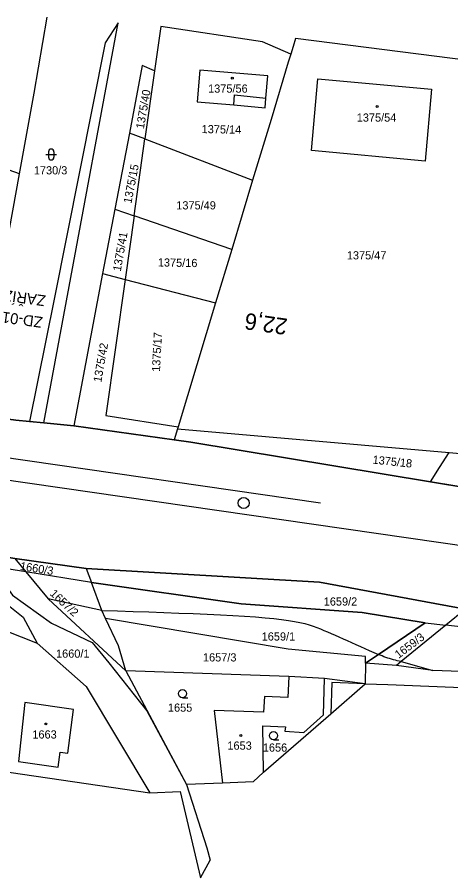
# Model space of a CAD drawing. Extents: x -757895 to -757311, y -1060303 to -1059942.
# Drawn here: x -757525.7 to -757446.3, y -1060221.2 to -1060063.5 of the extents above; entities that cross this region are included whole.
import ezdxf

# ---------------------------------------------------------------- set-up
doc = ezdxf.new("R2010")
doc.units = 0
for name, color, linetype in [('_hektaky', 7, 'Continuous'), ('_SO 102 hektometry', 7, 'Continuous'), ('Dočasné zábory - čísla', 7, 'Continuous'), ('Pozemky SŽDC', 7, 'Continuous'), ('Vrstva 1', 7, 'Continuous'), ('Vrstva 53', 7, 'Continuous'), ('Vrstva 55', 7, 'Continuous'), ('Vrstva 56', 7, 'Continuous'), ('Vrstva 57', 7, 'Continuous'), ('Vrstva 58', 7, 'Continuous'), ('Vrstva 59', 7, 'Continuous')]:
    doc.layers.add(name, color=color, linetype=linetype)

msp = doc.modelspace()

# ---------------------------------------------------------------- linework, layer by layer
at = {"layer": '_SO 102 hektometry'}
msp.add_circle((-757484.25, -1060152.51), 1, dxfattribs=at)
at = {"layer": 'Pozemky SŽDC'}
for points in [[(-757419.22, -1060153.71), (-757450.04, -1060148.6), (-757493.93, -1060141.33), (-757496.99, -1060140.91), (-757515.4, -1060138.37), (-757520.85, -1060137.84), (-757523.49, -1060137.59), (-757525.99, -1060137.35), (-757528.28, -1060137.03), (-757533.01, -1060136.32), (-757534.03, -1060136.19), (-757535.86, -1060133.35), (-757568.62, -1060130.44), (-757606.63, -1060125.23), (-757624.32, -1060124.22), (-757624.54, -1060126.42), (-757639.93, -1060124.17), (-757687.19, -1060114.38)], [(-757686.64, -1060138.39), (-757635.44, -1060145.86), (-757634.26, -1060145.96), (-757632.1, -1060146.3), (-757543.88, -1060160.4), (-757542.9, -1060160.49), (-757535.01, -1060161.18), (-757533.6, -1060161.43), (-757526.21, -1060162.71), (-757513.1, -1060164.5), (-757470.38, -1060167.04), (-757443.58, -1060171.99)]]:
    msp.add_lwpolyline(points, dxfattribs=at)
at = {"layer": 'Vrstva 1'}
for p, q in [((-757429.32, -1060162.53), (-757720.62, -1060120.47)), ((-757576.18, -1060137.2), (-757470.2, -1060152.45))]:
    msp.add_line(p, q, dxfattribs=at)
at = {"layer": 'Vrstva 53'}
for points in [[(-757687.19, -1060114.38), (-757639.93, -1060124.17), (-757624.54, -1060126.42), (-757624.32, -1060124.22), (-757612.89, -1060124.84), (-757606.63, -1060125.23), (-757568.62, -1060130.44), (-757535.86, -1060133.35), (-757534.03, -1060136.19), (-757533.01, -1060136.32), (-757528.28, -1060137.03), (-757525.99, -1060137.35), (-757523.49, -1060137.59), (-757520.85, -1060137.84), (-757515.4, -1060138.37), (-757496.99, -1060140.91), (-757493.93, -1060141.33), (-757450.04, -1060148.6), (-757417.66, -1060153.97), (-757412.43, -1060151.61), (-757391.89, -1060154.81), (-757390.25, -1060143), (-757387.56, -1060158.16)], [(-757328.56, -1060183.46), (-757338.29, -1060184.85), (-757361.91, -1060181.63), (-757443.58, -1060171.99), (-757470.38, -1060167.04), (-757513.1, -1060164.5), (-757526.21, -1060162.71), (-757533.6, -1060161.43), (-757535.01, -1060161.18), (-757542.9, -1060160.49), (-757543.88, -1060160.4), (-757632.1, -1060146.3), (-757634.26, -1060145.96), (-757635.44, -1060145.86), (-757686.64, -1060138.39), (-757693.18, -1060137.43), (-757732.62, -1060131.67), (-757793.56, -1060122.78), (-757866, -1060118.97)], [(-757509.58, -1060173.65), (-757510.26, -1060172.2), (-757512.14, -1060167.1), (-757484.68, -1060170.98), (-757462.52, -1060172.6), (-757450.99, -1060174.46), (-757459.56, -1060180.26), (-757461.95, -1060181.88), (-757461.94, -1060180.64), (-757476.1, -1060179.3), (-757509.58, -1060173.65)]]:
    msp.add_lwpolyline(points, dxfattribs=at)
at = {"layer": 'Vrstva 55'}
for p, q in [((-757522.65, -1060077.4), (-757520.23, -1060063.47)), ((-757499.45, -1060065.15), (-757500.59, -1060073.29)), ((-757480.83, -1060068), (-757499.45, -1060065.15)), ((-757475.63, -1060070.26), (-757480.83, -1060068)), ((-757474.75, -1060067.35), (-757475.21, -1060068.86)), ((-757425.51, -1060073.71), (-757474.75, -1060067.35)), ((-757475.21, -1060068.86), (-757475.63, -1060070.26)), ((-757525.35, -1060092.2), (-757579.91, -1060072.75)), ((-757502.84, -1060072.35), (-757505.19, -1060084.71)), ((-757500.59, -1060073.29), (-757502.84, -1060072.35)), ((-757500.59, -1060073.29), (-757502.35, -1060085.79)), ((-757525.35, -1060092.2), (-757522.65, -1060077.4)), ((-757505.19, -1060084.71), (-757507.85, -1060098.68)), ((-757502.35, -1060085.79), (-757505.19, -1060084.71)), ((-757504.33, -1060099.89), (-757502.35, -1060085.79)), ((-757502.35, -1060085.79), (-757482.61, -1060093.33)), ((-757527.8, -1060105.72), (-757525.35, -1060092.2)), ((-757482.61, -1060093.33), (-757486.45, -1060106.04)), ((-757507.85, -1060098.68), (-757510.09, -1060110.45)), ((-757507.85, -1060098.68), (-757504.33, -1060099.89)), ((-757504.33, -1060099.89), (-757505.97, -1060111.52)), ((-757486.45, -1060106.04), (-757504.33, -1060099.89)), ((-757486.45, -1060106.04), (-757489.4, -1060115.81)), ((-757510.09, -1060110.45), (-757515.4, -1060138.37)), ((-757510.09, -1060110.45), (-757505.97, -1060111.52)), ((-757505.97, -1060111.52), (-757489.4, -1060115.81)), ((-757489.4, -1060115.81), (-757496.27, -1060138.53)), ((-757515.4, -1060138.37), (-757496.99, -1060140.91)), ((-757496.4, -1060138.94), (-757496.99, -1060140.91)), ((-757496.27, -1060138.53), (-757496.4, -1060138.94)), ((-757496.4, -1060138.94), (-757446.57, -1060143.26)), ((-757450.04, -1060148.6), (-757417.66, -1060153.97)), ((-757526.21, -1060162.71), (-757513.1, -1060164.5)), ((-757513.1, -1060164.5), (-757512.14, -1060167.1)), ((-757443.58, -1060171.99), (-757447.18, -1060174.91)), ((-757507.2, -1060178.7), (-757509.58, -1060173.65)), ((-757450.99, -1060174.46), (-757447.18, -1060174.91)), ((-757505.82, -1060183.25), (-757507.2, -1060178.7)), ((-757461.95, -1060181.88), (-757461.97, -1060185.63)), ((-757456.27, -1060182.28), (-757461.95, -1060181.88)), ((-757475.98, -1060184.31), (-757505.82, -1060183.25)), ((-757505.82, -1060183.25), (-757494.7, -1060204.13)), ((-757449.6, -1060183.18), (-757456.27, -1060182.28)), ((-757469.46, -1060184.66), (-757475.98, -1060184.31)), ((-757461.97, -1060185.63), (-757469.46, -1060184.66)), ((-757468.3, -1060191.14), (-757461.97, -1060185.63)), ((-757461.97, -1060185.63), (-757457.81, -1060185.8)), ((-757457.81, -1060185.8), (-757442.84, -1060186.4)), ((-757480.62, -1060201.84), (-757468.3, -1060191.14)), ((-757553.73, -1060197.99), (-757501.45, -1060205.62)), ((-757482.5, -1060203.63), (-757480.62, -1060201.84)), ((-757488.16, -1060203.86), (-757494.7, -1060204.13)), ((-757482.5, -1060203.63), (-757488.16, -1060203.86)), ((-757492.15, -1060221.2), (-757490.36, -1060217.94))]:
    msp.add_line(p, q, dxfattribs=at)
for points in [[(-757475.63, -1060070.26), (-757476.07, -1060071.71), (-757479.24, -1060082.21), (-757482.61, -1060093.33)], [(-757486.06, -1060079.54), (-757480.34, -1060080.05), (-757480.18, -1060078.28), (-757479.84, -1060074.24), (-757492.3, -1060073.2), (-757492.76, -1060078.99), (-757486.06, -1060079.54)], [(-757470.67, -1060074.74), (-757449.81, -1060076.66), (-757451.01, -1060089.85), (-757471.85, -1060087.93), (-757470.67, -1060074.74)], [(-757446.57, -1060143.26), (-757435.09, -1060144.26), (-757425.51, -1060073.71)], [(-757505.97, -1060111.52), (-757509.48, -1060136.47), (-757496.27, -1060138.53)], [(-757515.4, -1060138.37), (-757518.94, -1060138.03), (-757520.85, -1060137.84), (-757523.49, -1060137.59), (-757525.99, -1060137.35)], [(-757496.99, -1060140.91), (-757493.93, -1060141.33), (-757450.04, -1060148.6)], [(-757450.04, -1060148.6), (-757448.35, -1060146), (-757446.57, -1060143.26)], [(-757535.4, -1060164.4), (-757534.05, -1060166.5), (-757527.72, -1060171), (-757524.67, -1060173.45), (-757522.06, -1060178.2)], [(-757530.47, -1060164.08), (-757526.6, -1060169.42), (-757519.47, -1060174.52), (-757512.04, -1060178.07), (-757508.94, -1060181.82), (-757502, -1060190.6), (-757494.7, -1060204.13)], [(-757512.14, -1060167.1), (-757524.18, -1060165.15), (-757527.62, -1060164.59), (-757530.47, -1060164.08)], [(-757513.1, -1060164.5), (-757470.38, -1060167.04), (-757443.58, -1060171.99)], [(-757450.99, -1060174.46), (-757462.52, -1060172.6), (-757484.68, -1060170.98), (-757512.14, -1060167.1)], [(-757509.58, -1060173.65), (-757510.26, -1060172.2), (-757512.14, -1060167.1)], [(-757541.4, -1060170.7), (-757539.76, -1060171.25), (-757522.06, -1060178.2)], [(-757461.95, -1060181.88), (-757461.94, -1060180.64), (-757476.1, -1060179.3), (-757509.58, -1060173.65)], [(-757461.95, -1060181.88), (-757459.56, -1060180.26), (-757450.99, -1060174.46)], [(-757447.18, -1060174.91), (-757455.39, -1060181.56), (-757456.27, -1060182.28)], [(-757373.86, -1060183.46), (-757405.36, -1060179.78), (-757434.52, -1060176.38), (-757447.18, -1060174.91)], [(-757522.06, -1060178.2), (-757513.1, -1060186.11), (-757501.45, -1060205.62)], [(-757373.35, -1060185.99), (-757375.27, -1060185.92), (-757449.6, -1060183.18)], [(-757475.98, -1060184.31), (-757476.19, -1060188.18), (-757480.46, -1060187.96), (-757480.61, -1060190.87), (-757489.65, -1060190.56), (-757488.16, -1060203.86)], [(-757480.62, -1060201.84), (-757480.75, -1060193.37), (-757476.57, -1060193.52), (-757476.69, -1060194.3), (-757473.22, -1060194.56), (-757469.64, -1060191.34), (-757469.46, -1060184.66)], [(-757525.5, -1060199.9), (-757518.26, -1060200.9), (-757517.87, -1060198.2), (-757516.44, -1060198.33), (-757515.46, -1060190.37), (-757524.35, -1060189.08), (-757525.5, -1060199.9)], [(-757494.7, -1060204.13), (-757490.98, -1060215.68), (-757490.36, -1060217.94)], [(-757501.45, -1060205.62), (-757495.89, -1060205.36), (-757492.15, -1060221.2)]]:
    msp.add_lwpolyline(points, dxfattribs=at)
at = {"layer": 'Vrstva 56'}
for p, q in [((-757516.7, -1060115.45), (-757507.27, -1060064.51)), ((-757507.27, -1060064.51), (-757509.6, -1060068.17)), ((-757509.6, -1060068.17), (-757518.99, -1060115.13)), ((-757486.06, -1060079.54), (-757485.91, -1060077.7)), ((-757485.91, -1060077.7), (-757480.18, -1060078.28)), ((-757518.99, -1060115.13), (-757523.49, -1060137.59)), ((-757520.85, -1060137.84), (-757516.7, -1060115.45)), ((-757526.21, -1060162.71), (-757524.18, -1060165.15)), ((-757524.18, -1060165.15), (-757520.05, -1060170.1)), ((-757520.05, -1060170.1), (-757505.82, -1060183.25)), ((-757510.26, -1060172.2), (-757520.05, -1060170.1)), ((-757455.39, -1060181.56), (-757449.6, -1060183.18)), ((-757468.07, -1060185.38), (-757468.3, -1060191.14)), ((-757461.97, -1060185.63), (-757468.07, -1060185.38))]:
    msp.add_line(p, q, dxfattribs=at)
for points in [[(-757510.26, -1060172.2), (-757507.38, -1060172.29), (-757504.48, -1060172.38), (-757501.65, -1060172.48), (-757498.87, -1060172.57), (-757496.13, -1060172.67), (-757493.5, -1060172.78), (-757490.97, -1060172.88), (-757488.52, -1060173), (-757486.24, -1060173.12), (-757484.11, -1060173.25), (-757482.11, -1060173.39), (-757480.33, -1060173.53), (-757478.74, -1060173.69), (-757477.31, -1060173.85), (-757476.06, -1060174.03), (-757474.95, -1060174.21), (-757473.95, -1060174.41), (-757473.07, -1060174.62), (-757472.28, -1060174.84), (-757471.54, -1060175.07), (-757470.86, -1060175.32), (-757470.2, -1060175.57), (-757469.55, -1060175.85), (-757468.9, -1060176.13), (-757468.22, -1060176.43), (-757467.51, -1060176.74), (-757466.79, -1060177.06), (-757466.04, -1060177.39), (-757465.27, -1060177.73), (-757464.48, -1060178.07), (-757463.69, -1060178.43), (-757462.87, -1060178.79), (-757462.05, -1060179.15), (-757461.23, -1060179.52), (-757460.39, -1060179.89), (-757459.56, -1060180.26)], [(-757455.39, -1060181.56), (-757455.75, -1060181.49), (-757456.1, -1060181.41), (-757456.46, -1060181.33), (-757456.81, -1060181.23), (-757457.16, -1060181.14), (-757457.51, -1060181.03), (-757457.86, -1060180.92), (-757458.2, -1060180.8), (-757458.55, -1060180.68), (-757458.89, -1060180.54), (-757459.22, -1060180.41), (-757459.56, -1060180.26)]]:
    msp.add_lwpolyline(points, dxfattribs=at)
at = {"layer": 'Vrstva 58'}
for p, q in [((-757520.52, -1060088.64), (-757518.52, -1060088.64)), ((-757520.02, -1060088.14), (-757520.02, -1060089.14)), ((-757519.02, -1060088.14), (-757519.02, -1060089.14)), ((-757495.47, -1060188.19), (-757494.47, -1060188.19)), ((-757478.79, -1060195.9), (-757477.79, -1060195.9))]:
    msp.add_line(p, q, dxfattribs=at)
for centre in [(-757495.47, -1060187.44), (-757478.79, -1060195.15)]:
    msp.add_circle(centre, 0.75, dxfattribs=at)
for centre, start, end in [((-757519.52, -1060088.14), 0, 180), ((-757519.52, -1060089.14), 180, 0)]:
    msp.add_arc(centre, 0.5, start, end, dxfattribs=at)
at = {"layer": 'Vrstva 59'}
for centre in [(-757486.33, -1060074.63), (-757459.78, -1060079.84), (-757520.49, -1060193.01), (-757484.78, -1060195.12)]:
    msp.add_circle(centre, 0.175, dxfattribs=at)

# ---------------------------------------------------------------- texts
at = {"layer": '_hektaky'}
msp.add_text('22,6', height=3, rotation=171.8129, dxfattribs=at).set_placement((-757476.09, -1060118.76))
at = {"layer": 'Dočasné zábory - čísla'}
for s, p in [('ZAŘÍZENÍ STAVENIŠTĚ', (-757520.45, -1060114.48)), ('ZD-01', (-757520.99, -1060118.44))]:
    msp.add_text(s, height=2, rotation=172.2261, dxfattribs=at).set_placement(p)
at = {"layer": 'Vrstva 57'}
for s, p in [('1375/56', (-757490.77, -1060077.3)), ('1375/54', (-757463.53, -1060082.61)), ('1730/3', (-757522.7, -1060092.28)), ('1375/49', (-757496.6, -1060098.7)), ('1375/47', (-757465.35, -1060107.86)), ('1659/2', (-757469.58, -1060171.31)), ('1659/1', (-757480.95, -1060177.72)), ('1660/1', (-757518.63, -1060180.86)), ('1657/3', (-757491.71, -1060181.55)), ('1655', (-757498.13, -1060190.76)), ('1663', (-757522.97, -1060195.68)), ('1653', (-757487.23, -1060197.72)), ('1656', (-757480.74, -1060198.08))]:
    msp.add_text(s, height=1.5, dxfattribs=at).set_placement(p)
for s, rotation, p in [('1375/40', 80, (-757502.55, -1060084.03)), ('1375/14', 359, (-757491.96, -1060084.71)), ('1375/15', 79, (-757504.83, -1060097.7)), ('1375/41', 80, (-757506.77, -1060110.13)), ('1375/16', 359, (-757499.99, -1060109.15)), ('1375/17', 87, (-757499.59, -1060128.49)), ('1375/42', 80, (-757510.34, -1060130.46)), ('1375/18', 354, (-757460.68, -1060145.28)), ('1660/3', 351, (-757525.3, -1060164.76)), ('1657/2', 317, (-757519.86, -1060169.27)), ('1659/3', 37, (-757455.86, -1060181.08))]:
    msp.add_text(s, height=1.5, rotation=rotation, dxfattribs=at).set_placement(p)

doc.saveas('drawing.dxf')
